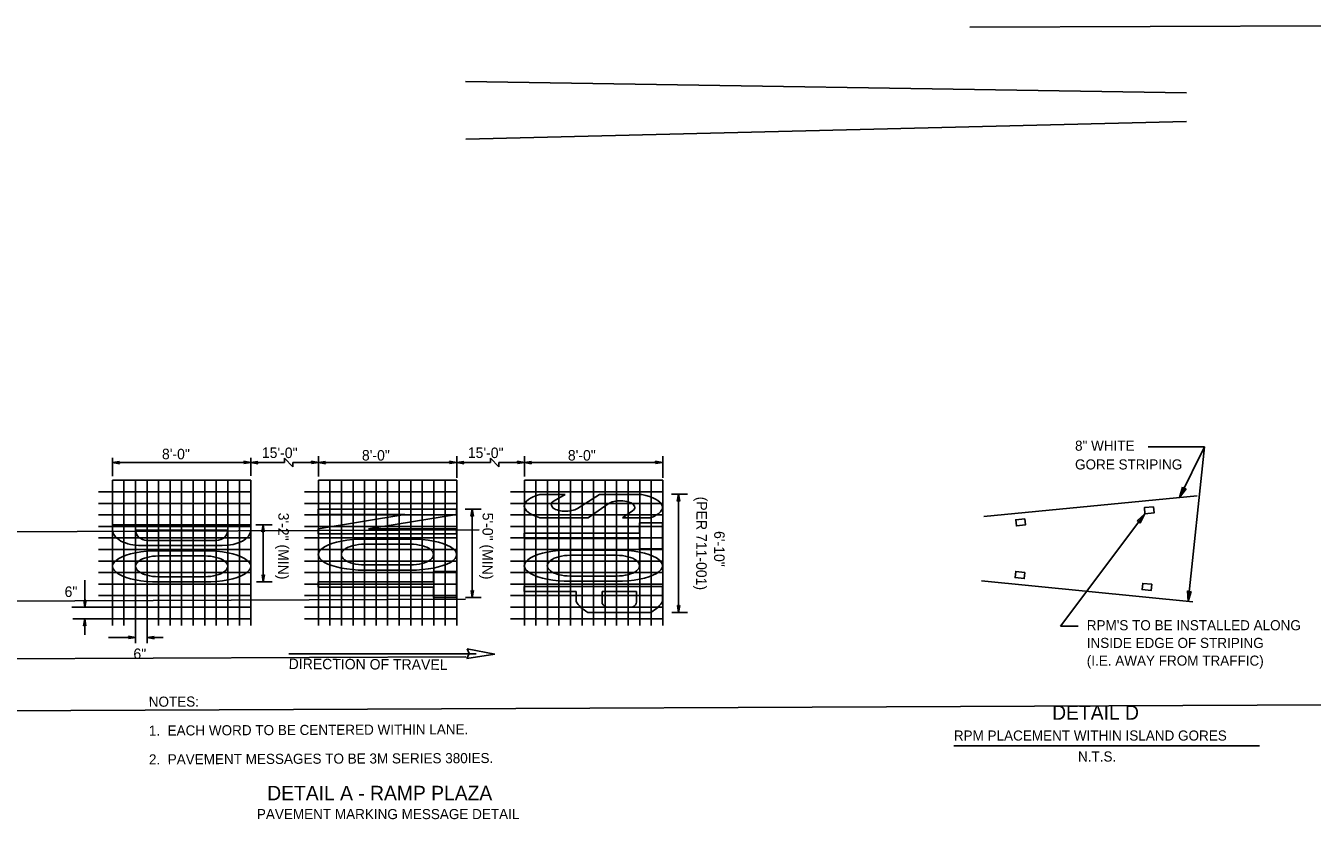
# Model space of a CAD drawing. Extents: x 583689 to 590775, y 1496016 to 1497365.
# Drawn here: x 587294 to 588186, y 1496787 to 1497337 of the extents above; entities that cross this region are included whole.
import ezdxf

# ---------------------------------------------------------------- set-up
doc = ezdxf.new("R2010")
doc.units = 0
for name, color, linetype in [('1', 7, 'Continuous'), ('12', 7, 'Continuous'), ('20', 7, 'Continuous'), ('21', 7, 'Continuous'), ('32', 7, 'Continuous'), ('5', 7, 'Continuous'), ('50', 7, 'Continuous'), ('52', 7, 'Continuous'), ('PavtMessage', 7, 'Continuous'), ('TextNotes', 7, 'Continuous')]:
    doc.layers.add(name, color=color, linetype=linetype)

msp = doc.modelspace()

# ---------------------------------------------------------------- linework, layer by layer
at = {"layer": '1'}
for points in [[(588075.82, 1497003.36), (588069.51, 1497002.74), (588069.93, 1496998.47), (588076.24, 1496999.09)], [(587986.62, 1496994.95), (587980.31, 1496994.33), (587980.73, 1496990.06), (587987.04, 1496990.68)], [(587986.66, 1496957.79), (587980.34, 1496958.42), (587979.91, 1496954.15), (587986.23, 1496953.52)], [(588074.73, 1496949.55), (588068.41, 1496950.18), (588067.98, 1496945.91), (588074.3, 1496945.28)]]:
    msp.add_lwpolyline(points, close=True, dxfattribs=at)
at = {"layer": '12'}
for p, q in [((588106.1, 1497011), (587958.1, 1496996.48)), ((587956.6, 1496952.04), (588103.15, 1496937.28))]:
    msp.add_line(p, q, dxfattribs=at)
at = {"layer": '20'}
for p, q in [((587599.7, 1496898.06), (587601.24, 1496901.44)), ((587619.12, 1496901.14), (587599.7, 1496898.06)), ((587599.82, 1496904.89), (587619.12, 1496901.14)), ((587601.24, 1496901.44), (587599.82, 1496904.89))]:
    msp.add_line(p, q, dxfattribs=at)
at = {"layer": '21'}
for p, q in [((587353.86, 1497037.2), (587353.86, 1497024.45)), ((587353.86, 1497034.01), (587358.71, 1497034.78)), ((587353.86, 1497034.01), (587358.51, 1497034.34)), ((587353.86, 1497034.01), (587449.86, 1497034.01)), ((587353.86, 1497034.01), (587358.68, 1497033.07)), ((587353.86, 1497034.01), (587358.5, 1497033.52)), ((587358.33, 1497033.93), (587358.71, 1497034.78)), ((587358.68, 1497033.07), (587358.33, 1497033.93)), ((587445.39, 1497034.09), (587445, 1497033.24)), ((587449.86, 1497034.01), (587445, 1497033.24)), ((587449.86, 1497034.01), (587445.03, 1497034.95)), ((587445.03, 1497034.95), (587445.39, 1497034.09)), ((587449.86, 1497034.01), (587445.21, 1497033.68)), ((587449.86, 1497034.01), (587445.22, 1497034.49)), ((587449.86, 1497037.2), (587449.86, 1497024.75)), ((587449.86, 1497034.01), (587454.71, 1497034.78)), ((587449.86, 1497034.01), (587454.51, 1497034.33)), ((587449.86, 1497034.01), (587454.68, 1497033.07)), ((587449.86, 1497034.01), (587454.5, 1497033.52)), ((587449.86, 1497034.01), (587473.28, 1497034.01)), ((587454.33, 1497033.93), (587454.71, 1497034.78)), ((587454.68, 1497033.07), (587454.33, 1497033.93)), ((587473.28, 1497034.01), (587473.27, 1497036.99)), ((587473.27, 1497036.99), (587479.04, 1497031.02)), ((587479.04, 1497034.01), (587479.04, 1497031.02)), ((587479.04, 1497034.01), (587496.7, 1497034.01)), ((587492.23, 1497034.09), (587491.84, 1497033.24)), ((587496.7, 1497034.01), (587491.84, 1497033.24)), ((587496.7, 1497034.01), (587491.87, 1497034.95)), ((587491.87, 1497034.95), (587492.23, 1497034.09)), ((587496.7, 1497034.01), (587492.05, 1497034.49)), ((587496.7, 1497034.01), (587492.05, 1497033.69)), ((587496.7, 1497038.33), (587496.69, 1497024.31)), ((587496.7, 1497034.01), (587501.55, 1497034.78)), ((587496.7, 1497034.01), (587501.35, 1497034.34)), ((587496.7, 1497034.01), (587592.45, 1497034.01)), ((587496.7, 1497034.01), (587501.52, 1497033.07)), ((587496.7, 1497034.01), (587501.34, 1497033.53)), ((587501.17, 1497033.93), (587501.55, 1497034.78)), ((587501.52, 1497033.07), (587501.17, 1497033.93)), ((587587.97, 1497034.09), (587587.59, 1497033.24)), ((587592.45, 1497034.01), (587587.59, 1497033.24)), ((587592.45, 1497034.01), (587587.62, 1497034.95)), ((587587.62, 1497034.95), (587587.97, 1497034.09)), ((587592.45, 1497034.01), (587587.79, 1497033.68)), ((587592.45, 1497034.01), (587587.8, 1497034.49)), ((587592.7, 1497038.34), (587592.7, 1497023.26)), ((587592.7, 1497035.72), (587592.7, 1497023.26)), ((587592.7, 1497034.01), (587597.55, 1497034.78)), ((587592.7, 1497034.01), (587597.34, 1497034.33)), ((587592.7, 1497034.01), (587616.12, 1497034.01)), ((587592.7, 1497034.01), (587597.52, 1497033.07)), ((587592.7, 1497034.01), (587597.34, 1497033.52)), ((587597.17, 1497033.93), (587597.55, 1497034.78)), ((587597.52, 1497033.07), (587597.17, 1497033.93)), ((587616.12, 1497034.01), (587616.11, 1497036.99)), ((587616.11, 1497036.99), (587621.88, 1497031.02)), ((587621.88, 1497034.01), (587621.88, 1497031.02)), ((587621.88, 1497034.01), (587639.53, 1497034.01)), ((587635.06, 1497034.09), (587634.68, 1497033.24)), ((587639.53, 1497034.01), (587634.68, 1497033.24)), ((587639.53, 1497034.01), (587634.71, 1497034.95)), ((587634.71, 1497034.95), (587635.06, 1497034.09)), ((587639.53, 1497034.01), (587634.88, 1497033.69)), ((587639.53, 1497034.01), (587634.89, 1497034.49)), ((587639.53, 1497038.33), (587639.53, 1497024.31)), ((587639.53, 1497034.01), (587644.39, 1497034.78)), ((587639.53, 1497034.01), (587644.19, 1497034.34)), ((587639.53, 1497034.01), (587735.28, 1497034.01)), ((587639.53, 1497034.01), (587644.36, 1497033.07)), ((587639.53, 1497034.01), (587644.18, 1497033.53)), ((587644.01, 1497033.93), (587644.39, 1497034.78)), ((587644.36, 1497033.07), (587644.01, 1497033.93)), ((587730.81, 1497034.09), (587730.43, 1497033.24)), ((587735.28, 1497034.01), (587730.43, 1497033.24)), ((587735.28, 1497034.01), (587730.46, 1497034.95)), ((587730.46, 1497034.95), (587730.81, 1497034.09)), ((587735.28, 1497034.01), (587730.63, 1497033.68)), ((587735.28, 1497034.01), (587730.64, 1497034.49)), ((587735.53, 1497038.34), (587735.53, 1497023.26)), ((587735.53, 1497035.72), (587735.53, 1497023.26)), ((587344.26, 1497013.66), (587449.86, 1497013.67)), ((587353.86, 1497021.66), (587449.86, 1497021.67)), ((587353.86, 1497021.67), (587353.86, 1496920.87)), ((587361.86, 1497021.67), (587361.86, 1496920.87)), ((587369.86, 1497021.67), (587369.86, 1496920.87)), ((587377.86, 1497021.67), (587377.86, 1496920.87)), ((587385.86, 1497021.67), (587385.86, 1496920.87)), ((587393.86, 1497021.67), (587393.86, 1496920.87)), ((587401.86, 1497021.67), (587401.86, 1496920.87)), ((587409.86, 1497021.67), (587409.86, 1496920.87)), ((587417.86, 1497021.67), (587417.86, 1496920.87)), ((587425.86, 1497021.67), (587425.86, 1496920.87)), ((587433.86, 1497021.67), (587433.86, 1496920.87)), ((587441.86, 1497021.67), (587441.86, 1496920.87)), ((587449.86, 1497021.67), (587449.86, 1496920.87)), ((587487.1, 1497013.67), (587592.7, 1497013.67)), ((587496.7, 1497021.67), (587592.7, 1497021.67)), ((587496.7, 1497021.67), (587496.7, 1496920.87)), ((587504.7, 1497021.67), (587504.7, 1496920.87)), ((587512.7, 1497021.67), (587512.7, 1496920.87)), ((587520.7, 1497021.67), (587520.7, 1496920.87)), ((587528.7, 1497021.67), (587528.7, 1496920.87)), ((587536.7, 1497021.67), (587536.7, 1496920.87)), ((587544.7, 1497021.67), (587544.7, 1496920.87)), ((587552.7, 1497021.67), (587552.7, 1496920.87)), ((587560.7, 1497021.67), (587560.7, 1496920.87)), ((587568.7, 1497021.67), (587568.7, 1496920.87)), ((587576.7, 1497021.67), (587576.7, 1496920.87)), ((587584.7, 1497021.67), (587584.7, 1496920.87)), ((587592.7, 1497021.67), (587592.7, 1496920.87)), ((587629.94, 1497013.67), (587735.53, 1497013.67)), ((587639.53, 1497021.67), (587735.53, 1497021.67)), ((587639.53, 1497021.67), (587639.53, 1496920.87)), ((587647.53, 1497021.67), (587647.53, 1496920.87)), ((587655.53, 1497021.67), (587655.53, 1496920.87)), ((587663.53, 1497021.67), (587663.53, 1496920.87)), ((587671.53, 1497021.67), (587671.53, 1496920.87)), ((587679.53, 1497021.67), (587679.53, 1496920.87)), ((587687.53, 1497021.67), (587687.53, 1496920.87)), ((587695.53, 1497021.67), (587695.53, 1496920.87)), ((587703.53, 1497021.67), (587703.53, 1496920.87)), ((587711.53, 1497021.67), (587711.53, 1496920.87)), ((587719.53, 1497021.67), (587719.53, 1496920.87)), ((587727.53, 1497021.67), (587727.53, 1496920.87)), ((587735.53, 1497021.67), (587735.53, 1496920.87)), ((587344.26, 1497005.66), (587449.86, 1497005.67)), ((587487.1, 1497005.67), (587592.7, 1497005.67)), ((587629.94, 1497005.67), (587735.53, 1497005.67)), ((587741.52, 1497012.07), (587752.73, 1497012.07)), ((587746.5, 1497012.07), (587745.56, 1497007.24)), ((587745.56, 1497007.24), (587746.42, 1497007.6)), ((587746.5, 1497012.07), (587746.02, 1497007.43)), ((587746.42, 1497007.6), (587747.27, 1497007.21)), ((587746.5, 1497012.07), (587746.5, 1496930.07)), ((587746.5, 1497012.07), (587747.27, 1497007.21)), ((587746.5, 1497012.07), (587746.83, 1497007.42)), ((587344.26, 1496997.66), (587449.86, 1496997.67)), ((587487.1, 1496997.67), (587592.7, 1496997.67)), ((587598.42, 1497001.6), (587609.63, 1497001.6)), ((587603.41, 1497001.61), (587602.47, 1496996.78)), ((587602.47, 1496996.78), (587603.33, 1496997.14)), ((587603.41, 1497001.61), (587602.92, 1496996.97)), ((587603.33, 1496997.14), (587604.18, 1496996.75)), ((587603.41, 1497001.61), (587604.18, 1496996.75)), ((587603.41, 1497001.61), (587603.73, 1496996.96)), ((587603.41, 1497001.61), (587603.41, 1496940.38)), ((587629.94, 1496997.67), (587735.53, 1496997.67)), ((587344.26, 1496989.66), (587449.86, 1496989.67)), ((587453.38, 1496990.8), (587464.59, 1496990.8)), ((587458.36, 1496990.78), (587457.43, 1496985.96)), ((587458.36, 1496990.78), (587457.88, 1496986.14)), ((587458.36, 1496990.78), (587459.13, 1496985.93)), ((587458.36, 1496990.78), (587458.69, 1496986.13)), ((587458.36, 1496990.78), (587458.36, 1496951.21)), ((587487.1, 1496989.67), (587592.7, 1496989.67)), ((587629.94, 1496989.67), (587735.53, 1496989.67)), ((587344.26, 1496981.66), (587449.86, 1496981.67)), ((587457.43, 1496985.96), (587458.29, 1496986.31)), ((587458.29, 1496986.31), (587459.13, 1496985.93)), ((587487.1, 1496981.67), (587592.7, 1496981.67)), ((587629.94, 1496981.67), (587735.53, 1496981.67)), ((587344.26, 1496973.66), (587449.86, 1496973.67)), ((587487.1, 1496973.67), (587592.7, 1496973.67)), ((587629.94, 1496973.67), (587735.53, 1496973.67)), ((587344.26, 1496965.66), (587449.86, 1496965.67)), ((587487.1, 1496965.67), (587592.7, 1496965.67)), ((587629.94, 1496965.67), (587735.53, 1496965.67)), ((587334.68, 1496933.66), (587334.68, 1496952.31)), ((587344.26, 1496957.66), (587449.86, 1496957.67)), ((587453.68, 1496951.2), (587464.58, 1496951.2)), ((587458.36, 1496951.21), (587457.59, 1496956.07)), ((587458.44, 1496955.68), (587457.59, 1496956.07)), ((587458.36, 1496951.21), (587458.04, 1496955.86)), ((587458.36, 1496951.21), (587459.3, 1496956.04)), ((587458.36, 1496951.21), (587458.85, 1496955.85)), ((587459.3, 1496956.04), (587458.44, 1496955.68)), ((587487.1, 1496957.67), (587592.7, 1496957.67)), ((587629.94, 1496957.67), (587735.54, 1496957.67)), ((587344.26, 1496949.66), (587449.86, 1496949.67)), ((587487.1, 1496949.67), (587592.7, 1496949.67)), ((587603.41, 1496940.38), (587602.64, 1496945.24)), ((587603.48, 1496944.85), (587602.64, 1496945.24)), ((587603.41, 1496940.38), (587603.08, 1496945.03)), ((587603.41, 1496940.38), (587604.34, 1496945.21)), ((587603.41, 1496940.38), (587603.89, 1496945.02)), ((587604.34, 1496945.21), (587603.48, 1496944.85)), ((587629.94, 1496949.67), (587735.54, 1496949.67)), ((587325.72, 1496933.66), (587344.26, 1496933.66)), ((587334.68, 1496933.66), (587333.91, 1496938.52)), ((587334.76, 1496938.13), (587333.91, 1496938.52)), ((587334.68, 1496933.66), (587334.35, 1496938.31)), ((587334.68, 1496933.66), (587335.61, 1496938.49)), ((587334.68, 1496933.66), (587335.16, 1496938.3)), ((587335.61, 1496938.49), (587334.76, 1496938.13)), ((587344.26, 1496941.66), (587449.86, 1496941.67)), ((587344.26, 1496933.66), (587449.86, 1496933.67)), ((587487.1, 1496941.67), (587592.7, 1496941.67)), ((587487.1, 1496933.67), (587592.7, 1496933.67)), ((587598.73, 1496940.38), (587609.63, 1496940.38)), ((587629.94, 1496941.67), (587735.54, 1496941.67)), ((587629.94, 1496933.67), (587735.54, 1496933.67)), ((587746.5, 1496930.07), (587745.73, 1496934.93)), ((587746.58, 1496934.54), (587745.73, 1496934.93)), ((587746.5, 1496930.07), (587746.17, 1496934.72)), ((587746.5, 1496930.07), (587747.44, 1496934.9)), ((587746.5, 1496930.07), (587746.99, 1496934.71)), ((587747.44, 1496934.9), (587746.58, 1496934.54)), ((587326.47, 1496925.62), (587344.26, 1496925.62)), ((587334.68, 1496925.62), (587333.74, 1496920.79)), ((587334.68, 1496925.62), (587334.19, 1496920.98)), ((587334.68, 1496914.43), (587334.68, 1496925.62)), ((587334.68, 1496925.62), (587335.45, 1496920.76)), ((587334.68, 1496925.62), (587335, 1496920.97)), ((587344.26, 1496925.66), (587449.86, 1496925.67)), ((587487.1, 1496925.67), (587592.7, 1496925.67)), ((587629.94, 1496925.67), (587735.54, 1496925.67)), ((587741.82, 1496930.06), (587752.73, 1496930.06)), ((587333.74, 1496920.79), (587334.6, 1496921.15)), ((587334.6, 1496921.15), (587335.45, 1496920.76)), ((587369.86, 1496908.82), (587369.86, 1496920.87)), ((587377.85, 1496908.82), (587377.86, 1496920.87)), ((587369.86, 1496912.66), (587351.21, 1496912.66)), ((587365.39, 1496912.74), (587365, 1496911.89)), ((587369.86, 1496912.66), (587365, 1496911.89)), ((587369.86, 1496912.66), (587365.03, 1496913.6)), ((587365.03, 1496913.6), (587365.39, 1496912.74)), ((587369.86, 1496912.66), (587365.21, 1496912.33)), ((587369.86, 1496912.66), (587365.22, 1496913.15)), ((587377.85, 1496912.66), (587382.71, 1496913.43)), ((587377.85, 1496912.66), (587382.5, 1496912.98)), ((587389.04, 1496912.66), (587377.85, 1496912.66)), ((587377.85, 1496912.66), (587382.68, 1496911.72)), ((587377.85, 1496912.66), (587382.49, 1496912.18)), ((587382.32, 1496912.59), (587382.71, 1496913.43)), ((587382.68, 1496911.72), (587382.32, 1496912.59)), ((587476.07, 1496901.29), (587606.06, 1496901.3))]:
    msp.add_line(p, q, dxfattribs=at)
at = {"layer": '5'}
for p, q in [((587948.53, 1497335.77), (588198.57, 1497336.88)), ((588098.73, 1497290.4), (587598.69, 1497298.22)), ((587598.86, 1497258.23), (588098.81, 1497270.47)), ((585969.09, 1496980.1), (587608.17, 1496987.35)), ((587598.69, 1496939.31), (583688.73, 1496922.03)), ((583688.9, 1496882.03), (587598.86, 1496899.31)), ((588199.06, 1496865.96), (586110.22, 1496856.73))]:
    msp.add_line(p, q, dxfattribs=at)
at = {"layer": '50'}
for p, q in [((588111.31, 1497044.79), (588072.15, 1497044.81)), ((588111.31, 1497044.79), (588093.99, 1497009.81)), ((588099.91, 1496937.6), (588111.31, 1497044.79)), ((588011.42, 1496920.49), (588069.93, 1496998.47)), ((588023.54, 1496920.49), (588011.42, 1496920.49)), ((587937.37, 1496837.41), (588149.42, 1496837.41))]:
    msp.add_line(p, q, dxfattribs=at)
at = {"layer": '52'}
for p, q in [((588096, 1497016.91), (588093.99, 1497009.81)), ((588093.99, 1497009.81), (588098.46, 1497015.69)), ((588096.96, 1497015.81), (588096, 1497016.91)), ((588098.46, 1497015.69), (588096.96, 1497015.81)), ((588069.93, 1496998.47), (588064.45, 1496993.51)), ((588066.65, 1496991.86), (588069.93, 1496998.47)), ((588064.45, 1496993.51), (588065.9, 1496993.11)), ((588065.9, 1496993.11), (588066.65, 1496991.86)), ((588100.62, 1496944.26), (588099.33, 1496944.95)), ((588099.33, 1496944.95), (588099.91, 1496937.6)), ((588099.91, 1496937.6), (588102.07, 1496944.66)), ((588102.07, 1496944.66), (588100.62, 1496944.26))]:
    msp.add_line(p, q, dxfattribs=at)
at = {"layer": 'PavtMessage'}
for p, q in [((587650.3, 1497011.92), (587667.76, 1497011.92)), ((587667.76, 1497011.92), (587660.19, 1497007.45)), ((587676.28, 1497002.12), (587691.72, 1497011.92)), ((587697.69, 1497005.37), (587683.87, 1496995.73)), ((587691.72, 1497011.92), (587721.05, 1497011.92)), ((587592.5, 1497001.61), (587496.64, 1497001.61)), ((587496.64, 1497001.61), (587496.64, 1496998.01)), ((587496.64, 1496998.01), (587556.55, 1496998.01)), ((587556.55, 1496998.01), (587496.64, 1496988.11)), ((587531.4, 1496988.11), (587592.5, 1496998.01)), ((587592.5, 1496998.01), (587592.5, 1497001.61)), ((587683.87, 1496995.73), (587650.3, 1496995.73)), ((587707.49, 1496995.73), (587714.41, 1497000.45)), ((587727.2, 1496995.73), (587707.49, 1496995.73)), ((587449.79, 1496990.78), (587353.93, 1496990.78)), ((587353.93, 1496990.78), (587353.93, 1496987.18)), ((587369.92, 1496987.18), (587433.83, 1496987.18)), ((587449.79, 1496987.18), (587449.79, 1496990.78)), ((587496.64, 1496988.11), (587496.64, 1496984.52)), ((587592.5, 1496988.11), (587531.4, 1496988.11)), ((587592.5, 1496984.52), (587592.5, 1496988.11)), ((587719.36, 1496992.13), (587735.34, 1496992.13)), ((587719.36, 1496984.94), (587719.36, 1496992.13)), ((587735.34, 1496992.13), (587735.34, 1496974.14)), ((587425.82, 1496979.99), (587377.89, 1496979.99)), ((587496.64, 1496984.52), (587592.5, 1496984.52)), ((587528.59, 1496980.92), (587560.55, 1496980.92)), ((587639.48, 1496981.34), (587639.48, 1496984.94)), ((587639.48, 1496984.94), (587719.36, 1496984.94)), ((587719.36, 1496981.34), (587639.48, 1496981.34)), ((587719.36, 1496974.14), (587719.36, 1496981.34)), ((587373.9, 1496976.39), (587429.82, 1496976.39)), ((587385.88, 1496972.79), (587417.84, 1496972.79)), ((587417.84, 1496969.2), (587385.88, 1496969.2)), ((587560.55, 1496977.32), (587528.59, 1496977.32)), ((587671.43, 1496973.24), (587703.39, 1496973.24)), ((587703.39, 1496969.64), (587671.43, 1496969.64)), ((587735.34, 1496974.14), (587719.36, 1496974.14)), ((587528.59, 1496962.93), (587560.55, 1496962.93)), ((587385.88, 1496954.8), (587417.84, 1496954.8)), ((587417.84, 1496951.21), (587385.88, 1496951.21)), ((587496.64, 1496947.58), (587496.64, 1496951.17)), ((587496.64, 1496951.17), (587576.53, 1496951.17)), ((587560.55, 1496959.33), (587528.59, 1496959.33)), ((587576.53, 1496958.37), (587592.5, 1496958.37)), ((587576.53, 1496951.17), (587576.53, 1496958.37)), ((587592.5, 1496958.37), (587592.5, 1496940.38)), ((587671.43, 1496955.25), (587703.39, 1496955.25)), ((587703.39, 1496951.65), (587671.43, 1496951.65)), ((587576.53, 1496947.58), (587496.64, 1496947.58)), ((587576.53, 1496940.38), (587576.53, 1496947.58)), ((587639.48, 1496948.06), (587735.34, 1496948.06)), ((587639.48, 1496944.46), (587639.48, 1496948.06)), ((587675.43, 1496944.46), (587639.48, 1496944.46)), ((587675.43, 1496937.57), (587675.43, 1496944.46)), ((587717.37, 1496944.46), (587693.4, 1496944.46)), ((587693.4, 1496944.46), (587693.4, 1496937.26)), ((587717.37, 1496937.26), (587717.37, 1496944.46)), ((587735.34, 1496948.06), (587735.34, 1496937.57)), ((587592.5, 1496940.38), (587576.53, 1496940.38)), ((587696.45, 1496933.67), (587714.32, 1496933.67)), ((587727.32, 1496930.07), (587683.45, 1496930.07))]:
    msp.add_line(p, q, dxfattribs=at)
for centre, major_axis, ratio, start_param, end_param in [((587671.43, 1497003.82), (-31.95, 0), 0.337782, 5.435123, 7.131247), ((587668.13, 1497004.72), (9.99, 0), 0.450376, 2.490106, 5.666015), ((587706.08, 1497002.92), (9.99, 0), 0.450376, 5.699287, 8.851109), ((587703.39, 1497002.92), (31.95, 0), 0.337782, 5.553458, 7.268296), ((587373.9, 1496987.18), (19.97, 0), 0.540451, 3.141593, 4.71335), ((587377.91, 1496987.18), (7.99, 0), 0.900751, 3.141593, 4.712389), ((587425.84, 1496987.18), (7.99, 0), 0.900751, 4.712389, 6.283185), ((587429.82, 1496987.18), (19.97, 0), 0.540451, 4.71335, 6.283185), ((587528.59, 1496970.12), (31.95, 0), 0.337782, 1.570796, 4.712389), ((587560.55, 1496970.12), (31.95, 0), 0.337782, 4.712389, 7.853982), ((587385.88, 1496962), (31.95, 0), 0.337782, 1.570796, 4.712389), ((587385.88, 1496962), (15.98, 0), 0.450376, 1.570796, 4.712389), ((587417.84, 1496962), (31.95, 0), 0.337782, 4.712389, 7.853982), ((587417.84, 1496962), (15.98, 0), 0.450376, 4.712389, 7.853982), ((587528.59, 1496970.12), (15.98, 0), 0.450376, 1.570796, 4.712389), ((587560.55, 1496970.12), (15.98, 0), 0.450376, 4.712389, 7.853982), ((587671.43, 1496962.45), (31.95, 0), 0.337782, 1.570796, 4.712389), ((587671.43, 1496962.45), (15.98, 0), 0.450376, 1.570796, 4.712389), ((587703.39, 1496962.45), (31.95, 0), 0.337782, 4.712389, 7.853982), ((587703.39, 1496962.45), (15.98, 0), 0.450376, 4.712389, 7.853982), ((587705.38, 1496944.46), (31.95, 0), 0.619266, 3.497014, 3.955933), ((587705.38, 1496937.26), (11.98, 0), 0.450376, 3.141593, 3.87132), ((587705.38, 1496937.26), (11.98, 0), 0.450376, 5.553458, 6.283185), ((587705.38, 1496944.46), (31.95, 0), 0.619266, 5.468845, 5.927764)]:
    msp.add_ellipse(centre, major_axis=major_axis, ratio=ratio, start_param=start_param, end_param=end_param, dxfattribs=at)

# ---------------------------------------------------------------- texts
at = {"layer": '20'}
for s, height, rotation, p in [(' 8\'-0"', 7.267, 359.70123, (587385.47, 1497036.31)), (' 15\'-0"', 7.267, 359.70123, (587454.76, 1497037.2)), (' 8\'-0"', 7.267, 359.70123, (587524.15, 1497035.41)), (' 15\'-0"', 7.267, 359.70123, (587597.6, 1497037.2)), (' 8\'-0"', 7.267, 359.70123, (587666.98, 1497035.41)), ('(PER 711-001)', 7.2669, 269.70123, (587758.97, 1497010.35)), ('3\'-2" (MIN)', 7.2669, 269.70123, (587468.93, 1496999.23)), ('5\'-0" (MIN)', 7.2669, 269.70123, (587610.57, 1496999.23)), ('6\'-10"', 7.267, 269.70123, (587771.2, 1496986.47)), ('6"', 7.267, 359.70123, (587320.65, 1496940.8)), ('6"', 7.267, 359.70123, (587368.38, 1496897.76)), ('DIRECTION OF TRAVEL', 7.2669, 359.70123, (587476.07, 1496890.76))]:
    msp.add_text(s, height=height, rotation=rotation, dxfattribs=at).set_placement(p)
at = {"layer": '32'}
for s, height, p in [('DETAIL A - RAMP PLAZA', 10, (587461.2, 1496799.78)), ('PAVEMENT MARKING MESSAGE DETAIL', 7, (587454.02, 1496786.69))]:
    msp.add_text(s, height=height, rotation=0.00473, dxfattribs=at).set_placement(p)
at = {"layer": '50'}
for s, height, p in [('8" WHITE', 7, (588021.44, 1497042.16)), ('GORE STRIPING', 7, (588021.44, 1497029.16)), ("RPM'S TO BE INSTALLED ALONG", 7, (588029.57, 1496917.67)), ('INSIDE EDGE OF STRIPING', 7, (588029.57, 1496905.39)), ('(I.E. AWAY FROM TRAFFIC)', 7, (588029.57, 1496893.11)), ('DETAIL D', 10, (588005.58, 1496855.62))]:
    msp.add_text(s, height=height, dxfattribs=at).set_placement(p)
for s, p in [('RPM PLACEMENT WITHIN ISLAND GORES', (587937.37, 1496841.17)), ('N.T.S.', (588023.48, 1496826.64))]:
    msp.add_text(s, height=7, rotation=359.99873, dxfattribs=at).set_placement(p)
at = {"layer": 'TextNotes'}
for s, p in [('NOTES:', (587379.03, 1496864.6)), ('1.  EACH WORD TO BE CENTERED WITHIN LANE.', (587379.11, 1496844.6)), ('2.  PAVEMENT MESSAGES TO BE 3M SERIES 380IES.', (587379.19, 1496824.61))]:
    msp.add_text(s, height=7, rotation=0.23586, dxfattribs=at).set_placement(p)

doc.saveas('drawing.dxf')
